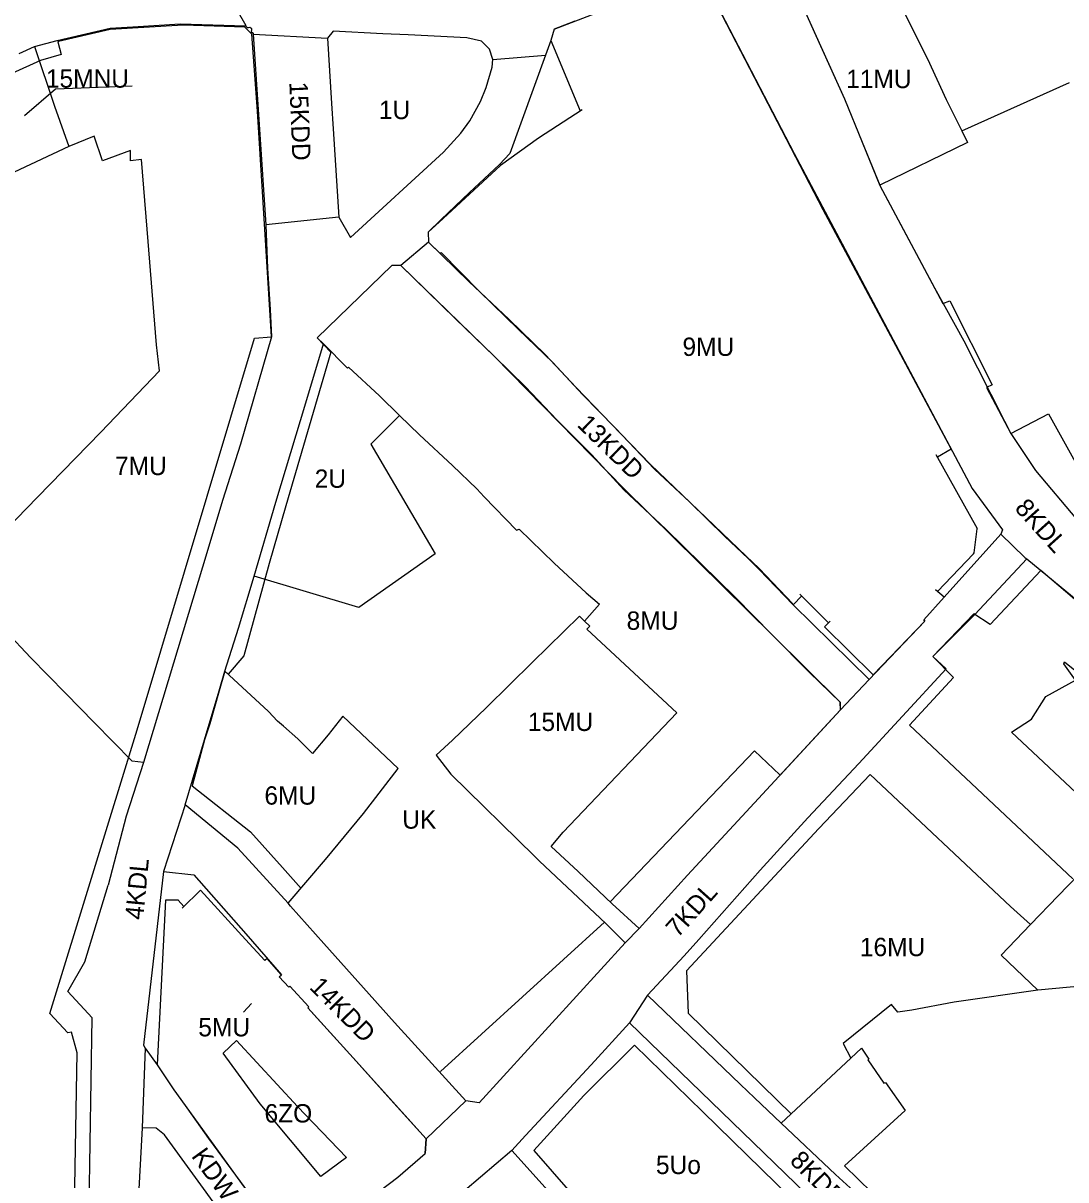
# Model space of a CAD drawing. Extents: x 7422310 to 7423642, y 5546060 to 5546927.
# Drawn here: x 7423055.8 to 7423340.1, y 5546433.5 to 5546749 of the extents above; entities that cross this region are included whole.
import ezdxf

# ---------------------------------------------------------------- set-up
doc = ezdxf.new("R2010")
doc.units = 0
for name, color, linetype in [('linie_rozgraniczajace', 7, 'Continuous'), ('linie_zabudowy_nieprzekraczalne', 7, 'Continuous'), ('linie_zabudowy_obowiązujace', 7, 'Continuous'), ('oznaczenia_przeznaczen', 7, 'Continuous')]:
    doc.layers.add(name, color=color, linetype=linetype)

msp = doc.modelspace()

# ---------------------------------------------------------------- linework, layer by layer
at = {"layer": 'linie_rozgraniczajace'}
for p, q in [((7423118.5, 5546745.96), (7423138.78, 5546744.9)), ((7423183.9, 5546739.12), (7423198.21, 5546740.25)), ((7423311.77, 5546719.6), (7423341.09, 5546732.82)), ((7423141.83, 5546696.06), (7423121.92, 5546694.04)), ((7423315.32, 5546587.73), (7423329.47, 5546602.89)), ((7423212.91, 5546590.54), (7423208.86, 5546585.95)), ((7423325.33, 5546555.64), (7423354.58, 5546528.06)), ((7423099.96, 5546535.83), (7423094.08, 5546517.59)), ((7423073.8, 5546425.75), (7423074.56, 5546477.74)), ((7423165.64, 5546444.75), (7423176.45, 5546455.05)), ((7423165.64, 5546444.75), (7423165.45, 5546440.76)), ((7423189.01, 5546441.58), (7423176.2, 5546430.66)), ((7423157.97, 5546434.29), (7423165.45, 5546440.76))]:
    msp.add_line(p, q, dxfattribs=at)
for points in [[(7423253.17, 5546793.01), (7423261.4, 5546771.18), (7423264.79, 5546762.18), (7423269.05, 5546752.12), (7423271.51, 5546746.62), (7423279.72, 5546728.32), (7423284.6, 5546716.54), (7423289.4, 5546704.82), (7423289.43, 5546704.77), (7423304.28, 5546676.79), (7423312.32, 5546662.39), (7423323.34, 5546640.42), (7423325.1, 5546637.07), (7423331.85, 5546627.01), (7423343.03, 5546613.72), (7423350.76, 5546605.4), (7423362.12, 5546595.91), (7423372.22, 5546584.99), (7423379.9, 5546578.3), (7423393.21, 5546566.45), (7423401.86, 5546559.12), (7423407.66, 5546553.66), (7423421.28, 5546541.81)], [(7423240.19, 5546763.19), (7423266.06, 5546713.44), (7423314.53, 5546622.05), (7423322.84, 5546610.83), (7423322.39, 5546609.67), (7423328.96, 5546603.31), (7423329.47, 5546602.89), (7423365.29, 5546573.4), (7423407.54, 5546534.03), (7423414.38, 5546525.69), (7423415.93, 5546520.64), (7423414.51, 5546505.88), (7423413.36, 5546490.66), (7423413.26, 5546489.25), (7423413.16, 5546487.99)], [(7423054.69, 5546740.72), (7423058.92, 5546742.6), (7423065.05, 5546744.25), (7423079.51, 5546747.66), (7423085.73, 5546747.99), (7423098.63, 5546748.82), (7423116.42, 5546748.26), (7423116.57, 5546748.25), (7423110, 5546759.93)], [(7423200.6, 5546747.34), (7423224.53, 5546756.68), (7423237.36, 5546761.98)], [(7423291.16, 5546761.62), (7423302.34, 5546739.27), (7423307.49, 5546728.16), (7423311.77, 5546719.6)], [(7423116.42, 5546748.26), (7423116.89, 5546747.79), (7423117.2, 5546747.86), (7423117.6, 5546747.87), (7423117.85, 5546747.75), (7423118.02, 5546747.51), (7423118.03, 5546747.15), (7423117.93, 5546746.77), (7423118.48, 5546746.3), (7423118.5, 5546745.96), (7423121.92, 5546694.04), (7423122.4, 5546682.1), (7423123.15, 5546670.94), (7423123.46, 5546663.44), (7423115.01, 5546634.2), (7423110.17, 5546618.85), (7423106.1, 5546605.41), (7423088.62, 5546547.39), (7423083.84, 5546532.68), (7423078.94, 5546513.92)], [(7423200.6, 5546747.34), (7423199.69, 5546744.3), (7423198.21, 5546740.25), (7423188.45, 5546713.46)], [(7423058.92, 5546742.6), (7423064.37, 5546726.4), (7423068.24, 5546715.33)], [(7423311.77, 5546719.6), (7423313.31, 5546716.44), (7423289.4, 5546704.82)], [(7423048.23, 5546608.02), (7423059.72, 5546619.68), (7423076.93, 5546637.43), (7423092.96, 5546654.18), (7423092.17, 5546661.26), (7423089.64, 5546692.78), (7423088.08, 5546711.79), (7423085.08, 5546711.41), (7423085.06, 5546714.25), (7423077.44, 5546711.42), (7423075.19, 5546718.15), (7423068.24, 5546715.33), (7423053.34, 5546708.35)], [(7423188.45, 5546713.46), (7423185.71, 5546710.47), (7423177.45, 5546702.83), (7423169.65, 5546695.37), (7423166.26, 5546691.98), (7423166.29, 5546689.26), (7423158.74, 5546682.9), (7423156.3, 5546682.89), (7423135.98, 5546663.21), (7423137.69, 5546661.55)], [(7423286.52, 5546569.96), (7423265.77, 5546590.39), (7423256.5, 5546599.98), (7423253.5, 5546603.02), (7423247.07, 5546609.11), (7423237.53, 5546618.36), (7423227.93, 5546627.38), (7423217.34, 5546638.56), (7423208.28, 5546647.76), (7423200.18, 5546656.44), (7423190.8, 5546665.57), (7423180.21, 5546675.79), (7423169.74, 5546686.44), (7423169.51, 5546686.2), (7423166.29, 5546689.26)], [(7423158.74, 5546682.9), (7423173.56, 5546668.41), (7423184.28, 5546658.07), (7423192.79, 5546649.84), (7423201.44, 5546640.74), (7423210.81, 5546631.25), (7423219.54, 5546621.68), (7423231.04, 5546610.99), (7423240.66, 5546601.56), (7423249.94, 5546592.41), (7423259.99, 5546582.18), (7423270.22, 5546571.87), (7423278.6, 5546563.82), (7423278.59, 5546561.66)], [(7423158.42, 5546642.01), (7423163.84, 5546636.72), (7423172.84, 5546628.33), (7423179.45, 5546622.03), (7423181.47, 5546619.84), (7423190.33, 5546610.69), (7423191, 5546611.01), (7423200.61, 5546601.72), (7423209.3, 5546593.62), (7423212.91, 5546590.54)], [(7423322.39, 5546609.67), (7423306.93, 5546592.43), (7423301.35, 5546586.3), (7423301.63, 5546585.91), (7423286.52, 5546569.96), (7423278.59, 5546561.66), (7423252.93, 5546533.87), (7423236.97, 5546516.59), (7423223.76, 5546502.11), (7423219.92, 5546498.16)], [(7423088.62, 5546547.39), (7423085.49, 5546547.74), (7423075.14, 5546558.24), (7423067.43, 5546566.16), (7423057.78, 5546575.97), (7423037.77, 5546597.26)], [(7423208.86, 5546585.95), (7423207.5, 5546587.24), (7423194.64, 5546574.72), (7423182.14, 5546562.33), (7423172.87, 5546553.48), (7423168.36, 5546549.39), (7423172.39, 5546544.14), (7423195.2, 5546521.79), (7423196.6, 5546520.47), (7423214.63, 5546503.48), (7423219.92, 5546498.16), (7423180.15, 5546454.53), (7423176.45, 5546455.05), (7423157.07, 5546476.47), (7423147.09, 5546487.59), (7423137.78, 5546497.95), (7423128.66, 5546508.16), (7423128.04, 5546508.96), (7423138.25, 5546520.91), (7423148.56, 5546533.48), (7423158.02, 5546545.69), (7423142.93, 5546560.02), (7423138.98, 5546554.89), (7423134.66, 5546549.81), (7423130.66, 5546553.83), (7423126.81, 5546557.27), (7423125.13, 5546558.65), (7423122.67, 5546561.28), (7423110.77, 5546572.27), (7423114.51, 5546584.03), (7423118.8, 5546598.15)], [(7423283.63, 5546547.12), (7423307.45, 5546572.91), (7423303.8, 5546576.3), (7423314.99, 5546587.92), (7423315.32, 5546587.73)], [(7423223.76, 5546502.11), (7423216.43, 5546508.83), (7423207.16, 5546517.61), (7423199.8, 5546524.48), (7423203.02, 5546528.39), (7423234.01, 5546560.9), (7423209.53, 5546583.76), (7423210.32, 5546584.57), (7423208.86, 5546585.95)], [(7423325.33, 5546555.64), (7423330.75, 5546559.21), (7423334.65, 5546565.38), (7423342.73, 5546569.81), (7423339.55, 5546574.28), (7423339.74, 5546574.79), (7423348.06, 5546568.11), (7423356.39, 5546561.43), (7423357.09, 5546562.48), (7423366.34, 5546554.09), (7423374.52, 5546546.12), (7423358.6, 5546533.87), (7423365.16, 5546524.96), (7423373.4, 5546511.72), (7423377.83, 5546504.65), (7423381.95, 5546489.88), (7423376.21, 5546489.3), (7423374.83, 5546489.18), (7423369.66, 5546488.71), (7423332.49, 5546485.31), (7423322.5, 5546494.79), (7423330.44, 5546503.18), (7423338.04, 5546511.01), (7423354.58, 5546528.06)], [(7423128.04, 5546508.96), (7423114.35, 5546524.03), (7423099.96, 5546535.83), (7423105.27, 5546553.57), (7423109.22, 5546566.92), (7423110.77, 5546572.27)], [(7423313.75, 5546400.32), (7423298.5, 5546415.11), (7423285.3, 5546427.74), (7423277.34, 5546435.03), (7423262.5, 5546448.96), (7423255.17, 5546455.86), (7423251.35, 5546459.53), (7423226, 5546483.92), (7423236.03, 5546494.6), (7423239.99, 5546499.12), (7423256.78, 5546518), (7423269.78, 5546532.29), (7423283.63, 5546547.12)], [(7423094.08, 5546517.59), (7423088.56, 5546470.25), (7423089.1, 5546469.47), (7423088.2, 5546447.7)], [(7423094.08, 5546517.59), (7423102.37, 5546516.72), (7423116.48, 5546500.6), (7423126.24, 5546489.45)], [(7423074.56, 5546477.74), (7423068.01, 5546484.86), (7423072.56, 5546492.99), (7423078.94, 5546513.92)], [(7423165.64, 5546444.75), (7423156.03, 5546455.39), (7423145.77, 5546466.8), (7423135.96, 5546477.66), (7423133.38, 5546480.45), (7423133.67, 5546480.72), (7423128.49, 5546486.34), (7423128.2, 5546486.07), (7423125.57, 5546488.87), (7423126.24, 5546489.45)], [(7423226, 5546483.92), (7423221.13, 5546476.36), (7423210.64, 5546464.93), (7423192.78, 5546445.64), (7423189.01, 5546441.58), (7423225.4, 5546401.19), (7423232.87, 5546392.89), (7423245.09, 5546379.05), (7423251.02, 5546372.38), (7423263.59, 5546358.66), (7423274.33, 5546346.76), (7423280.39, 5546339.82)], [(7423332.49, 5546485.31), (7423309.69, 5546482.03), (7423298.09, 5546479.79), (7423294.26, 5546479.25), (7423292.55, 5546481.37), (7423279.41, 5546470.72), (7423281.46, 5546466.71), (7423262.5, 5546448.96)], [(7423221.13, 5546476.36), (7423246.19, 5546452.06), (7423272.22, 5546426.88), (7423291.22, 5546408.42), (7423309.4, 5546390.63), (7423315.98, 5546384.15), (7423320.29, 5546380.02), (7423325.04, 5546370.95), (7423326.71, 5546365.57), (7423328.94, 5546358.36), (7423329.06, 5546357.09), (7423331.4, 5546347.59)], [(7423089.1, 5546469.47), (7423092.3, 5546464.88), (7423096.86, 5546458.12), (7423100.38, 5546453.19), (7423106.34, 5546444.85), (7423118.48, 5546428.31), (7423128.61, 5546414.21), (7423153, 5546430.51), (7423157.97, 5546434.29)], [(7423117.54, 5546413.93), (7423094.37, 5546445.85), (7423092.01, 5546447.67), (7423088.2, 5546447.7), (7423087.01, 5546425.95), (7423086.77, 5546421.45), (7423095.13, 5546416.2), (7423117.54, 5546413.93)]]:
    msp.add_lwpolyline(points, dxfattribs=at)
for points in [[(7423140.33, 5546746.78), (7423138.78, 5546744.9), (7423139.89, 5546727.12), (7423140.28, 5546720.21), (7423141.83, 5546696.06), (7423145.07, 5546690.5), (7423170.36, 5546713.84), (7423175.17, 5546719.04), (7423177.54, 5546722.37), (7423180.49, 5546727.67), (7423182.04, 5546731.41), (7423183.71, 5546736.97), (7423183.9, 5546739.12), (7423182.95, 5546741.92), (7423180.73, 5546744.06), (7423176.79, 5546745.02), (7423160.76, 5546745.78), (7423153.82, 5546746.12)], [(7423137.69, 5546661.55), (7423144.21, 5546654.9), (7423144.49, 5546655.17), (7423152.91, 5546647.38), (7423158.42, 5546642.01), (7423150.59, 5546634.17), (7423168.16, 5546604.26), (7423147.34, 5546589.59), (7423118.8, 5546598.15), (7423124.73, 5546618.36), (7423132.88, 5546645.42)], [(7423110.31, 5546468.1), (7423113.98, 5546471.53), (7423130.63, 5546453.52), (7423143.99, 5546439.67), (7423136.93, 5546434.45), (7423120.42, 5546454.28)]]:
    msp.add_lwpolyline(points, close=True, dxfattribs=at)
at = {"layer": 'linie_zabudowy_nieprzekraczalne'}
for p, q in [((7423065.27, 5546743.94), (7423066.11, 5546740.49)), ((7423118.85, 5546663.08), (7423123.46, 5546663.44)), ((7423320.04, 5546650.36), (7423318.51, 5546649.63)), ((7423111.7, 5546571.41), (7423110.77, 5546572.27)), ((7423063.03, 5546478.89), (7423086.84, 5546556.26)), ((7423297.51, 5546557.56), (7423342.04, 5546515.64)), ((7423067.93, 5546473.66), (7423063.03, 5546478.89)), ((7423068.99, 5546473.81), (7423067.93, 5546473.66)), ((7423286.14, 5546466.27), (7423286.37, 5546466.48))]:
    msp.add_line(p, q, dxfattribs=at)
for points in [[(7423079.55, 5546747.31), (7423065.43, 5546743.98), (7423065.27, 5546743.94), (7423065.54, 5546742.79)], [(7423066.11, 5546740.49), (7423060.55, 5546738.86), (7423043.75, 5546731.25)], [(7423289.43, 5546704.77), (7423306.6, 5546672.5), (7423308.46, 5546673.3)], [(7423318.68, 5546649.71), (7423318.51, 5546649.63), (7423325.1, 5546637.07), (7423335.35, 5546642.45), (7423344.93, 5546625.25), (7423367.95, 5546638.08), (7423372.99, 5546666.05), (7423376.68, 5546689.1), (7423380.45, 5546690.93)], [(7423308.46, 5546673.3), (7423320.04, 5546650.36)], [(7423086.84, 5546556.26), (7423086.84, 5546556.26), (7423118.85, 5546663.08)], [(7423139.68, 5546659.29), (7423127.39, 5546617.37), (7423122.91, 5546601.63)], [(7423122.91, 5546601.63), (7423115.92, 5546576.44), (7423111.7, 5546571.41)], [(7423333.33, 5546599.75), (7423319.47, 5546584.98), (7423315.02, 5546587.94)], [(7423265.77, 5546590.39), (7423265.77, 5546590.39)], [(7423315.32, 5546587.73), (7423303.8, 5546576.3)], [(7423303.8, 5546576.3), (7423309.48, 5546570.57), (7423297.51, 5546557.56)], [(7423110.77, 5546572.27), (7423109.22, 5546566.92), (7423109.22, 5546566.92), (7423106.65, 5546557.95), (7423105.27, 5546553.57), (7423105.27, 5546553.57), (7423105.27, 5546553.57), (7423101.88, 5546541.03), (7423117.79, 5546528.42), (7423126.46, 5546518.76), (7423131.6, 5546513.04)], [(7423215.87, 5546509.4), (7423255.21, 5546550.55), (7423262.09, 5546543.97)], [(7423286.79, 5546544.07), (7423272.77, 5546529.39), (7423236.67, 5546490.57)], [(7423330.44, 5546503.18), (7423325.02, 5546508.08), (7423325.02, 5546508.08), (7423286.79, 5546544.07)], [(7423169.63, 5546463.11), (7423214.33, 5546503.77), (7423214.33, 5546503.77)], [(7423236.67, 5546490.57), (7423237.1, 5546478.98), (7423265.27, 5546451.49)], [(7423118.01, 5546481.6), (7423115.87, 5546479.25)], [(7423069.83, 5546426.53), (7423070.49, 5546468.22), (7423068.99, 5546473.81)], [(7423241.08, 5546452.13), (7423222.53, 5546470.3), (7423208.63, 5546456.53)], [(7423281.46, 5546466.71), (7423284.36, 5546469.44), (7423286.37, 5546466.48)], [(7423286.14, 5546466.27), (7423290.52, 5546459.87), (7423290.97, 5546460.06), (7423296.27, 5546452.49), (7423279.78, 5546437.34)], [(7423208.63, 5546456.53), (7423195.04, 5546441.5), (7423228.09, 5546403.61), (7423232.68, 5546398.29), (7423253.71, 5546418.3), (7423265.12, 5546428.67), (7423241.08, 5546452.13)]]:
    msp.add_lwpolyline(points, dxfattribs=at)
at = {"layer": 'linie_zabudowy_obowiązujace'}
for p, q in [((7423118.11, 5546745.98), (7423116.26, 5546747.92)), ((7423200.6, 5546747.34), (7423199.66, 5546744.23)), ((7423196.32, 5546717.68), (7423185.95, 5546710.2)), ((7423166.26, 5546691.98), (7423166.29, 5546689.26)), ((7423158.74, 5546682.9), (7423156.3, 5546682.89)), ((7423315.99, 5546611.06), (7423304.76, 5546631.31)), ((7423305.09, 5546630.75), (7423308.84, 5546632.91)), ((7423315.08, 5546604.5), (7423315.95, 5546611.09)), ((7423344.95, 5546589.85), (7423333.33, 5546599.75)), ((7423265.77, 5546590.39), (7423268.08, 5546592.78)), ((7423267.61, 5546593.23), (7423275.42, 5546585.48)), ((7423306.93, 5546592.43), (7423304.58, 5546594.42)), ((7423275.87, 5546585.94), (7423274.31, 5546584.34)), ((7423274.31, 5546584.34), (7423287.54, 5546571.31)), ((7423287.54, 5546571.31), (7423301.63, 5546585.91)), ((7423301.63, 5546585.91), (7423301.35, 5546586.3)), ((7423278.68, 5546561.76), (7423278.6, 5546563.82)), ((7423104.14, 5546512.58), (7423099.15, 5546507.61)), ((7423098.14, 5546509.81), (7423094.57, 5546509.85)), ((7423099.64, 5546508.05), (7423098.03, 5546509.85)), ((7423279.78, 5546437.34), (7423308.74, 5546409.07))]:
    msp.add_line(p, q, dxfattribs=at)
for points in [[(7423308.84, 5546632.91), (7423273.89, 5546698.07), (7423240.19, 5546763.19)], [(7423269.05, 5546752.12), (7423279.72, 5546728.32), (7423284.6, 5546716.54), (7423289.43, 5546704.77)], [(7423116.26, 5546747.92), (7423099.42, 5546748.44), (7423079.55, 5546747.31)], [(7423206.21, 5546749.58), (7423200.6, 5546747.34)], [(7423119.65, 5546724.96), (7423118.11, 5546745.98)], [(7423199.69, 5546744.3), (7423207.63, 5546725.08)], [(7423208.23, 5546725.33), (7423196.32, 5546717.68)], [(7423123.46, 5546663.44), (7423119.65, 5546724.96)], [(7423185.95, 5546710.2), (7423170.27, 5546695.69)], [(7423170.27, 5546695.69), (7423166.26, 5546691.98)], [(7423166.29, 5546689.26), (7423177.34, 5546678.52), (7423188.3, 5546668.21), (7423198.13, 5546658.6), (7423206.54, 5546649.65), (7423216.14, 5546639.76), (7423226.84, 5546628.61), (7423252.98, 5546603.64), (7423256.47, 5546600.3), (7423265.68, 5546590.59)], [(7423156.3, 5546682.89), (7423135.98, 5546663.21)], [(7423278.6, 5546563.82), (7423259.99, 5546582.18), (7423219.63, 5546621.98), (7423184.28, 5546658.07), (7423158.74, 5546682.9)], [(7423135.98, 5546663.21), (7423139.68, 5546659.29)], [(7423305.08, 5546594), (7423314.95, 5546604.27), (7423315.08, 5546604.5)], [(7423301.68, 5546585.9), (7423301.35, 5546586.3), (7423306.93, 5546592.43)], [(7423262.18, 5546543.92), (7423278.68, 5546561.76)], [(7423165.64, 5546444.75), (7423145.77, 5546466.8), (7423133.38, 5546480.45), (7423133.67, 5546480.72), (7423128.49, 5546486.34), (7423128.2, 5546486.07), (7423125.57, 5546488.87), (7423126.24, 5546489.45), (7423122.32, 5546493.9), (7423121.68, 5546493.34), (7423116.4, 5546499.05), (7423104.14, 5546512.58)], [(7423094.57, 5546509.85), (7423092.31, 5546464.97)], [(7423092.31, 5546465.07), (7423092.3, 5546464.88), (7423096.86, 5546458.12)], [(7423096.86, 5546458.12), (7423128.61, 5546414.21)], [(7423165.45, 5546440.76), (7423165.64, 5546444.75)], [(7423128.61, 5546414.21), (7423153, 5546430.51), (7423157.97, 5546434.29), (7423165.45, 5546440.76)]]:
    msp.add_lwpolyline(points, dxfattribs=at)
at = {"layer": 'oznaczenia_przeznaczen'}
msp.add_lwpolyline([(7423085.47, 5546731.82), (7423064.58, 5546730.97), (7423056.14, 5546723.76)], dxfattribs=at)

# ---------------------------------------------------------------- texts
for s, p in [('15MNU', (7423061.98, 5546731.41)), ('11MU', (7423280.2, 5546731.28)), ('1U', (7423152.78, 5546722.83)), ('9MU', (7423235.57, 5546658.25)), ('7MU', (7423080.82, 5546625.74)), ('2U', (7423135.28, 5546622.28)), ('8MU', (7423220.34, 5546583.56)), ('15MU', (7423193.4, 5546555.96)), ('6MU', (7423121.58, 5546535.87)), ('UK', (7423159.16, 5546529.31)), ('16MU', (7423283.94, 5546494.54)), ('5MU', (7423103.54, 5546472.66)), ('6ZO', (7423121.6, 5546449.18)), ('5Uo', (7423228.33, 5546435.11))]:
    msp.add_text(s, height=5, dxfattribs=at).set_placement(p)
for s, rotation, p in [('15KDD', 272.2906, (7423128.36, 5546732.94)), ('13KDD', 315.6936, (7423206.6, 5546639.2)), ('8KDL', 311.9656, (7423325.93, 5546616.53)), ('4KDL', 84.5876, (7423088.51, 5546504.32)), ('7KDL', 48.1372, (7423234.29, 5546499.33)), ('14KDD', 314.7904, (7423133.58, 5546485.87)), ('KDW', 305.7049, (7423101.48, 5546439.98)), ('8KDD', 314.5873, (7423264.58, 5546438.47))]:
    msp.add_text(s, height=5, rotation=rotation, dxfattribs=at).set_placement(p)

doc.saveas('drawing.dxf')
